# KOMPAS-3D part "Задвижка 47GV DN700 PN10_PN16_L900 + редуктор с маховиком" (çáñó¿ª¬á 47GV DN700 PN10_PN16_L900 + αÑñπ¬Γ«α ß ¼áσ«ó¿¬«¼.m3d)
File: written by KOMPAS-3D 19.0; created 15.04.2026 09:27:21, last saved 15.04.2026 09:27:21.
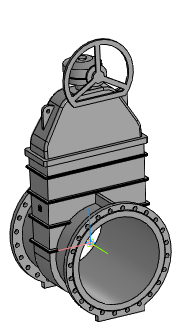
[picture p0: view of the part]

Document properties: Автор: Энергия; Полное имя файла: ..\..\Задвижка 47GV DN700 PN10_L900 + редуктор с маховиком.a3d

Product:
- Part/product: Задвижка 47GV DN700 PN10_PN16_L900 + редуктор с маховиком
    Масса: 2246.56

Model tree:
1. Операция без истории:1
